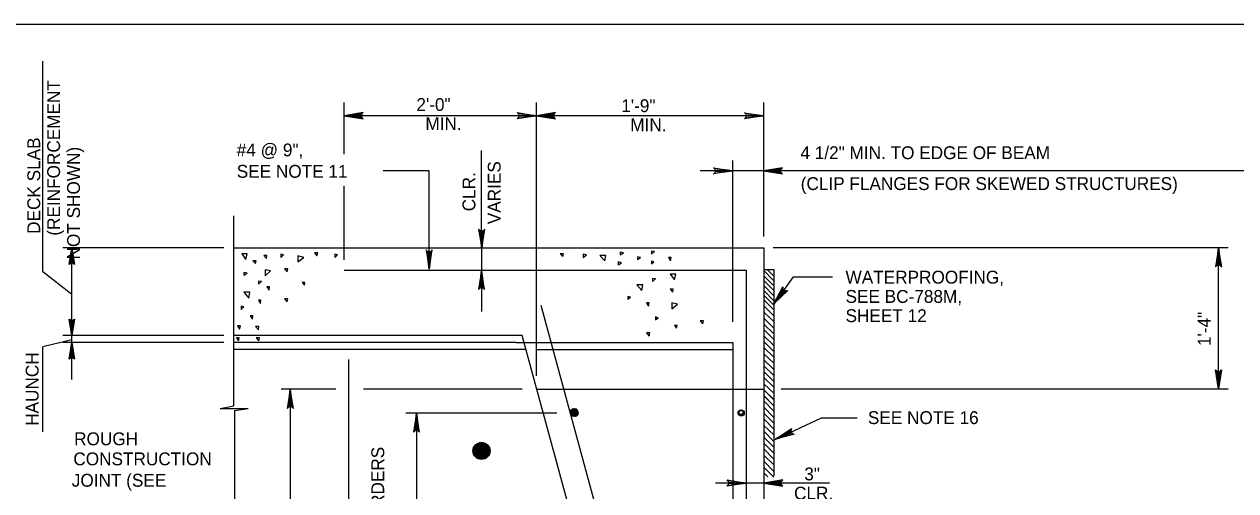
# Model space of a CAD drawing. Extents: x 640009 to 641706, y 298547 to 299735.
# Drawn here: x 640364.1 to 640646.9, y 299017.2 to 299126.2 of the extents above; entities that cross this region are included whole.
import ezdxf

# ---------------------------------------------------------------- set-up
doc = ezdxf.new("R2010")
doc.units = 0
doc.layers.add('1', color=7, linetype='Continuous')

msp = doc.modelspace()

# ---------------------------------------------------------------- linework, layer by layer
at = {"layer": '1'}
for p, q in [((640049.47, 299126.17), (640835.47, 299126.17)), ((640049.47, 299126.17), (640835.47, 299126.17)), ((640368.44, 299068.35), (640368.44, 299117.52)), ((640438.74, 299095.82), (640438.74, 299107.9)), ((640483.65, 299044.02), (640483.65, 299107.9)), ((640536.74, 299076.59), (640536.74, 299107.9)), ((640536.74, 299104.8), (640438.74, 299104.8)), ((640470.86, 299073.94), (640470.86, 299096.68)), ((640529.49, 299056.66), (640529.49, 299094.31)), ((640458.61, 299091.94), (640447.88, 299091.94)), ((640458.61, 299068.94), (640458.61, 299091.94)), ((640529.49, 299091.94), (640521.86, 299091.94)), ((640651.24, 299091.94), (640529.49, 299091.94)), ((640438.74, 299071.13), (640438.74, 299088.4)), ((640412.99, 299037.06), (640412.99, 299081.44)), ((640410.67, 299073.94), (640373.07, 299073.94)), ((640375.21, 299043.2), (640375.21, 299073.94)), ((640412.99, 299073.94), (640536.74, 299073.94)), ((640470.86, 299073.94), (640470.86, 299059.06)), ((640536.74, 299073.94), (640536.74, 299040.94)), ((640536.74, 299073.94), (640536.74, 298959.5)), ((640645.18, 299073.94), (640538.94, 299073.94)), ((640642.91, 299040.94), (640642.91, 299073.94)), ((640375.21, 299063.01), (640368.44, 299068.35)), ((640438.74, 299068.69), (640532.61, 299068.69)), ((640474.74, 299068.69), (640477.26, 299068.69)), ((640532.61, 299068.69), (640532.61, 299014.94)), ((640536.74, 299068.9), (640539.11, 299068.9)), ((640539.11, 299068.9), (640539.11, 299020.68)), ((640539.11, 299060.74), (640543.65, 299067.15)), ((640543.65, 299067.15), (640552.82, 299067.15)), ((640508.11, 298974.56), (640484.77, 299060.46)), ((640375.21, 299052.46), (640368.44, 299050.81)), ((640410.67, 299053.44), (640373.07, 299053.44)), ((640480.36, 299053.44), (640412.99, 299053.44)), ((640505.86, 298959.56), (640480.36, 299053.44)), ((640368.44, 299030.96), (640368.44, 299050.81)), ((640410.67, 299051.81), (640373.07, 299051.81)), ((640478.86, 299051.81), (640412.99, 299051.81)), ((640481.24, 299050.19), (640412.99, 299050.19)), ((640478.86, 299051.81), (640529.49, 299051.81)), ((640483.74, 299050.19), (640529.49, 299050.19)), ((640529.49, 299051.81), (640529.49, 298963.44)), ((640439.82, 299047.83), (640439.82, 298971.99)), ((640436.87, 299040.94), (640424.1, 299040.94)), ((640426.23, 299015.32), (640426.23, 299040.94)), ((640480.33, 299040.94), (640443.31, 299040.94)), ((640483.74, 299040.94), (640536.74, 299040.94)), ((640645.18, 299040.94), (640540.8, 299040.94)), ((640409.86, 299036.44), (640412.99, 299037.06)), ((640409.86, 299036.44), (640416.36, 299036.44)), ((640413.11, 299036.44), (640413.11, 299036.44)), ((640413.24, 299035.94), (640416.36, 299036.44)), ((640413.24, 298985.94), (640413.24, 299035.94)), ((640488.45, 299035.31), (640453.19, 299035.31)), ((640455.68, 299035.31), (640455.68, 298963.44)), ((640539.43, 299029.19), (640550.08, 299034.15)), ((640558.55, 299034.15), (640550.08, 299034.15)), ((640552.11, 299019.01), (640525.47, 299019.01))]:
    msp.add_line(p, q, dxfattribs=at)
for points in [[(640442.98, 299105.34), (640442.8, 299105.02), (640438.74, 299104.8), (640442.98, 299105.34), (640443.19, 299105.52), (640438.74, 299104.8), (640442.8, 299104.6), (640442.96, 299104.3), (640438.74, 299104.8), (640443.19, 299104.07), (640442.96, 299104.3)], [(640479.4, 299105.34), (640479.58, 299105.02), (640483.65, 299104.8), (640479.4, 299105.34), (640479.19, 299105.52), (640483.65, 299104.8), (640479.58, 299104.6), (640479.42, 299104.3), (640483.65, 299104.8), (640479.19, 299104.07), (640479.42, 299104.3)], [(640487.89, 299105.34), (640487.72, 299105.02), (640483.65, 299104.8), (640487.89, 299105.34), (640488.1, 299105.52), (640483.65, 299104.8), (640487.72, 299104.6), (640487.88, 299104.3), (640483.65, 299104.8), (640488.1, 299104.07), (640487.88, 299104.3)], [(640532.45, 299105.32), (640532.62, 299105), (640536.69, 299104.78), (640532.45, 299105.32), (640532.24, 299105.51), (640536.69, 299104.78), (640532.62, 299104.58), (640532.46, 299104.28), (640536.69, 299104.78), (640532.24, 299104.06), (640532.46, 299104.28)], [(640525.2, 299092.46), (640525.37, 299092.14), (640529.44, 299091.92), (640525.2, 299092.46), (640524.99, 299092.65), (640529.44, 299091.92), (640525.37, 299091.72), (640525.21, 299091.42), (640529.44, 299091.92), (640524.99, 299091.2), (640525.21, 299091.42)], [(640540.9, 299092.46), (640540.73, 299092.14), (640536.66, 299091.92), (640540.9, 299092.46), (640541.11, 299092.65), (640536.66, 299091.92), (640540.73, 299091.72), (640540.88, 299091.42), (640536.66, 299091.92), (640541.11, 299091.2), (640540.88, 299091.42)], [(640470.34, 299078.1), (640470.66, 299077.93), (640470.88, 299073.86), (640470.34, 299078.1), (640470.15, 299078.31), (640470.88, 299073.86), (640471.08, 299077.93), (640471.38, 299078.08), (640470.88, 299073.86), (640471.6, 299078.31), (640471.38, 299078.08)], [(640374.71, 299070.19), (640375.09, 299070.31), (640375.21, 299073.94), (640374.71, 299070.19), (640374.59, 299070.06), (640375.21, 299073.94), (640375.46, 299070.31), (640375.71, 299070.19), (640375.21, 299073.94), (640375.84, 299070.06), (640375.71, 299070.19)], [(640458.09, 299073.23), (640458.41, 299073.05), (640458.63, 299068.98), (640458.09, 299073.23), (640457.9, 299073.44), (640458.63, 299068.98), (640458.83, 299073.05), (640459.13, 299073.21), (640458.63, 299068.98), (640459.35, 299073.44), (640459.13, 299073.21)], [(640643.45, 299069.69), (640643.14, 299069.87), (640642.91, 299073.94), (640643.45, 299069.69), (640643.64, 299069.48), (640642.91, 299073.94), (640642.72, 299069.87), (640642.41, 299069.71), (640642.91, 299073.94), (640642.19, 299069.48), (640642.41, 299069.71)], [(640471.38, 299064.4), (640471.07, 299064.57), (640470.85, 299068.64), (640471.38, 299064.4), (640471.57, 299064.19), (640470.85, 299068.64), (640470.65, 299064.57), (640470.34, 299064.42), (640470.85, 299068.64), (640470.12, 299064.19), (640470.34, 299064.42)], [(640539.12, 299066.26), (640536.68, 299068.7)], [(640539.11, 299065.07), (640536.74, 299067.44)], [(640539.11, 299067.33), (640537.54, 299068.9)], [(640539.16, 299062.69), (640536.72, 299065.13)], [(640539.19, 299063.89), (640536.75, 299066.33)], [(640539.11, 299061.57), (640536.82, 299063.86)], [(640542.05, 299063.93), (640541.69, 299063.97), (640539.1, 299060.83), (640542.05, 299063.93), (640542.32, 299063.99), (640539.1, 299060.83), (640541.35, 299064.22), (640541.2, 299064.53), (640539.1, 299060.83), (640541.15, 299064.85), (640541.2, 299064.53)], [(640539.18, 299059.35), (640536.74, 299061.79)], [(640539.11, 299060.54), (640536.75, 299062.9)], [(640539.18, 299057.97), (640536.8, 299060.35)], [(640539.18, 299056.62), (640536.8, 299058.85)], [(640375.71, 299057.19), (640375.46, 299057.06), (640375.21, 299053.44), (640375.71, 299057.19), (640375.84, 299057.31), (640375.21, 299053.44), (640375.09, 299057.06), (640374.84, 299057.19), (640375.21, 299053.44), (640374.59, 299057.31), (640374.84, 299057.19)], [(640539.14, 299053.74), (640536.77, 299056.11)], [(640539.14, 299055.13), (640536.8, 299057.47)], [(640539.18, 299055.1), (640536.8, 299057.47)], [(640539.14, 299052.48), (640536.77, 299054.85)], [(640539.14, 299051.02), (640536.77, 299053.4)], [(640374.71, 299048.06), (640375.09, 299048.19), (640375.21, 299051.81), (640374.71, 299048.06), (640374.59, 299047.94), (640375.21, 299051.81), (640375.46, 299048.19), (640375.71, 299048.06), (640375.21, 299051.81), (640375.84, 299047.94), (640375.71, 299048.06)], [(640539.14, 299049.66), (640536.77, 299052.04)], [(640539.14, 299048.29), (640536.77, 299050.66)], [(640539.14, 299046.93), (640536.77, 299049.16)], [(640539.14, 299045.41), (640536.77, 299047.79)], [(640539.14, 299044.04), (640536.77, 299046.41)], [(640539.14, 299042.66), (640536.77, 299045.04)], [(640643.44, 299045.23), (640643.12, 299045.05), (640642.9, 299040.98), (640643.44, 299045.23), (640643.62, 299045.44), (640642.9, 299040.98), (640642.7, 299045.05), (640642.4, 299045.21), (640642.9, 299040.98), (640642.17, 299045.44), (640642.4, 299045.21)], [(640539.14, 299041.29), (640536.77, 299043.66)], [(640539.14, 299039.93), (640536.77, 299042.16)], [(640426.75, 299036.65), (640426.43, 299036.82), (640426.21, 299040.89), (640426.75, 299036.65), (640426.93, 299036.44), (640426.21, 299040.89), (640426.01, 299036.82), (640425.71, 299036.67), (640426.21, 299040.89), (640425.49, 299036.44), (640425.71, 299036.67)], [(640539.11, 299037.05), (640536.74, 299039.43)], [(640539.11, 299038.44), (640536.77, 299040.79)], [(640539.14, 299038.41), (640536.77, 299040.79)], [(640538.18, 299038), (640536.77, 299039.41)], [(640491.61, 299035.44), (640492.49, 299036.44)], [(640491.61, 299035.19), (640492.86, 299036.44)], [(640491.61, 299035.19), (640492.74, 299036.44)], [(640491.61, 299035.31), (640492.61, 299036.44)], [(640491.61, 299035.44), (640492.49, 299036.44)], [(640491.61, 299035.56), (640492.36, 299036.44)], [(640491.61, 299035.69), (640492.24, 299036.44)], [(640491.61, 299035.94), (640492.11, 299036.31)], [(640491.74, 299034.94), (640493.11, 299036.31)], [(640491.74, 299034.94), (640492.99, 299036.31)], [(640491.74, 299035.06), (640492.86, 299036.31)], [(640491.86, 299034.81), (640493.24, 299036.19)], [(640491.86, 299034.81), (640493.11, 299036.19)], [(640491.99, 299034.69), (640493.24, 299036.06)], [(640491.99, 299034.69), (640493.24, 299036.06)], [(640492.11, 299034.56), (640493.36, 299035.94)], [(640492.11, 299034.56), (640493.36, 299035.94)], [(640492.11, 299034.69), (640493.36, 299035.94)], [(640492.24, 299034.56), (640493.36, 299035.81)], [(640492.36, 299034.56), (640493.49, 299035.69)], [(640492.49, 299034.56), (640493.49, 299035.56)], [(640492.61, 299034.56), (640493.49, 299035.56)], [(640492.74, 299034.56), (640493.49, 299035.44)], [(640539.11, 299035.79), (640536.74, 299038.17)], [(640539.11, 299034.33), (640536.74, 299036.71)], [(640536.81, 299038), (640536.77, 299038.04)], [(640456.21, 299031.07), (640455.9, 299031.24), (640455.68, 299035.31), (640456.21, 299031.07), (640456.4, 299030.86), (640455.68, 299035.31), (640455.48, 299031.24), (640455.17, 299031.09), (640455.68, 299035.31), (640454.95, 299030.86), (640455.17, 299031.09)], [(640492.86, 299034.56), (640493.49, 299035.19)], [(640493.11, 299034.69), (640493.36, 299034.94)], [(640539.11, 299032.98), (640536.74, 299035.35)], [(640539.11, 299031.6), (640536.74, 299033.98)], [(640539.11, 299030.25), (640536.74, 299032.48)], [(640539.11, 299028.73), (640536.74, 299031.1)], [(640543.56, 299030.5), (640543.27, 299030.72), (640539.47, 299029.27), (640543.56, 299030.5), (640543.83, 299030.42), (640539.47, 299029.27), (640543.1, 299031.1), (640543.12, 299031.45), (640539.47, 299029.27), (640543.24, 299031.74), (640543.12, 299031.45)], [(640468.98, 299025.98), (640468.87, 299026.6), (640469.09, 299027.33), (640469.76, 299028.1), (640470.41, 299028.37), (640471.19, 299028.38), (640472.06, 299027.98), (640472.57, 299027.39), (640472.74, 299026.75), (640472.71, 299026.02), (640472.41, 299025.39), (640472.01, 299024.96), (640471.41, 299024.68), (640470.75, 299024.56), (640470.12, 299024.72), (640469.59, 299025.03), (640469.17, 299025.54), (640468.99, 299025.98), (640469, 299027.11), (640469.08, 299025.75), (640469.09, 299027.38), (640469.2, 299025.39), (640469.23, 299027.6), (640469.32, 299025.3), (640469.34, 299027.73), (640469.42, 299025.17), (640469.47, 299027.88), (640469.54, 299025.04), (640469.57, 299028), (640469.66, 299024.98), (640469.67, 299028.05), (640469.74, 299024.89), (640469.76, 299028.16), (640469.8, 299024.85), (640469.86, 299028.19), (640469.9, 299024.81), (640469.93, 299028.24), (640469.98, 299024.77), (640470.01, 299028.29), (640470.09, 299024.66), (640470.09, 299028.32), (640470.21, 299024.65), (640470.15, 299028.34), (640470.34, 299024.62), (640470.28, 299028.38), (640470.49, 299024.58), (640470.38, 299028.39), (640470.43, 299024.6), (640470.47, 299028.44), (640470.58, 299024.57), (640470.57, 299028.43), (640470.67, 299024.55), (640470.65, 299028.45), (640470.75, 299024.54), (640470.72, 299028.45), (640470.88, 299024.57), (640470.82, 299028.45), (640470.97, 299024.55), (640470.92, 299028.48), (640470.82, 299024.54), (640471, 299028.45), (640471.05, 299024.56), (640471.09, 299028.47), (640471.13, 299024.57), (640471.18, 299028.43), (640471.21, 299024.58), (640471.26, 299028.41), (640471.31, 299024.61), (640471.33, 299028.39), (640471.4, 299024.63), (640471.42, 299028.37), (640471.5, 299024.69), (640471.51, 299028.36), (640471.59, 299024.71), (640471.57, 299028.32), (640471.68, 299024.73), (640471.65, 299028.27), (640471.77, 299024.79), (640471.74, 299028.25), (640471.84, 299024.84), (640471.83, 299028.2), (640471.91, 299024.86), (640471.93, 299028.14), (640471.99, 299024.93), (640472, 299028.09), (640472.05, 299024.99), (640472.09, 299028.01), (640472.15, 299025.08), (640472.19, 299027.9), (640472.26, 299025.17), (640472.29, 299027.78), (640472.4, 299025.31), (640472.36, 299027.7), (640472.52, 299025.55), (640472.47, 299027.61), (640472.47, 299025.48), (640472.54, 299027.48), (640472.57, 299025.63), (640472.63, 299027.31), (640472.64, 299025.76), (640472.7, 299027.11)], [(640472.7, 299027.11), (640472.79, 299026.42), (640472.12, 299025.39), (640470.74, 299024.76), (640469.18, 299025.69), (640469.02, 299027.04), (640470.22, 299028.08), (640471.5, 299028.08), (640472.45, 299027.42), (640472.66, 299026.34), (640472.02, 299025.12), (640472.39, 299025.56), (640470.35, 299024.79), (640469.22, 299025.52), (640468.91, 299026.59), (640469.27, 299027.39), (640470.04, 299028.06), (640470.68, 299028.35), (640471.94, 299028)], [(640539.11, 299027.35), (640536.74, 299029.73)], [(640539.11, 299025.98), (640536.74, 299028.35)], [(640539.11, 299024.6), (640536.74, 299026.98)], [(640539.11, 299023.25), (640536.74, 299025.48)], [(640539.11, 299021.73), (640536.74, 299024.1)], [(640539.11, 299020.35), (640536.74, 299022.73)], [(640537.67, 299020.42), (640536.74, 299021.35)], [(640528.37, 299019.54), (640528.54, 299019.23), (640532.61, 299019.01), (640528.37, 299019.54), (640528.16, 299019.73), (640532.61, 299019.01), (640528.54, 299018.81), (640528.38, 299018.5), (640532.61, 299019.01), (640528.16, 299018.28), (640528.38, 299018.5)], [(640540.98, 299019.54), (640540.8, 299019.23), (640536.74, 299019.01), (640540.98, 299019.54), (640541.19, 299019.73), (640536.74, 299019.01), (640540.8, 299018.81), (640540.96, 299018.5), (640536.74, 299019.01), (640541.19, 299018.28), (640540.96, 299018.5)]]:
    msp.add_lwpolyline(points, dxfattribs=at)
for points in [[(640414.86, 299072.56), (640415.86, 299071.19), (640416.11, 299072.56)], [(640419.99, 299072.19), (640420.61, 299071.44), (640420.74, 299072.19)], [(640423.99, 299071.69), (640424.61, 299072.31), (640423.99, 299072.44)], [(640431.86, 299072.81), (640432.36, 299072.06), (640432.61, 299072.81)], [(640436.61, 299071.69), (640437.24, 299072.31), (640436.61, 299072.44)], [(640489.24, 299072.56), (640489.86, 299071.94), (640489.99, 299072.56)], [(640494.61, 299071.69), (640495.36, 299072.31), (640494.61, 299072.44)], [(640498.49, 299072.19), (640499.61, 299070.94), (640499.86, 299072.19)], [(640503.24, 299072.31), (640503.99, 299072.81), (640503.24, 299072.94)], [(640510.49, 299072.44), (640511.24, 299073.06), (640510.49, 299073.19)], [(640417.49, 299070.94), (640418.11, 299070.31), (640418.24, 299070.94)], [(640427.99, 299070.69), (640429.36, 299071.69), (640427.99, 299072.06)], [(640502.74, 299069.94), (640503.49, 299070.44), (640502.74, 299070.69)], [(640507.24, 299071.19), (640507.99, 299071.69), (640507.24, 299071.81)], [(640510.49, 299070.19), (640511.11, 299070.69), (640510.49, 299070.81)], [(640514.49, 299071.69), (640514.99, 299070.94), (640515.11, 299071.69)], [(640415.36, 299067.56), (640416.11, 299068.06), (640415.36, 299068.19)], [(640420.36, 299067.44), (640421.61, 299068.56), (640420.36, 299068.81)], [(640424.86, 299069.06), (640425.49, 299068.31), (640425.61, 299069.06)], [(640510.74, 299066.06), (640511.49, 299066.69), (640510.74, 299066.81)], [(640514.86, 299067.81), (640515.86, 299066.44), (640516.24, 299067.81)], [(640418.74, 299065.44), (640419.49, 299066.06), (640418.74, 299066.19)], [(640420.74, 299064.81), (640421.24, 299064.06), (640421.36, 299064.81)], [(640428.99, 299065.81), (640429.49, 299065.19), (640429.61, 299065.81)], [(640507.11, 299065.31), (640508.24, 299063.94), (640508.49, 299065.31)], [(640514.86, 299064.31), (640515.49, 299063.56), (640515.61, 299064.31)], [(640415.36, 299063.56), (640416.49, 299062.19), (640416.74, 299063.56)], [(640418.74, 299061.69), (640419.24, 299060.94), (640419.36, 299061.69)], [(640424.86, 299062.06), (640425.49, 299061.31), (640425.61, 299062.06)], [(640504.99, 299061.94), (640505.61, 299062.44), (640504.99, 299062.56)], [(640509.36, 299061.06), (640509.86, 299060.31), (640509.99, 299061.06)], [(640515.24, 299059.69), (640516.61, 299060.81), (640515.24, 299061.06)], [(640414.74, 299059.56), (640415.36, 299060.19), (640414.74, 299060.31)], [(640416.86, 299058.06), (640417.36, 299057.31), (640417.49, 299058.06)], [(640413.86, 299055.69), (640414.36, 299054.94), (640414.61, 299055.69)], [(640418.11, 299055.56), (640418.74, 299054.81), (640418.86, 299055.56)], [(640511.43, 299057.11), (640512.06, 299057.61), (640511.43, 299057.86)], [(640515.86, 299055.81), (640516.36, 299055.19), (640516.49, 299055.81)], [(640521.89, 299056.91), (640522.52, 299056.16), (640522.64, 299056.91)], [(640413.61, 299052.94), (640414.11, 299052.19), (640414.24, 299052.94)], [(640418.24, 299052.94), (640418.86, 299052.19), (640418.99, 299052.94)], [(640509.36, 299054.06), (640509.99, 299053.31), (640510.11, 299054.06)]]:
    msp.add_lwpolyline(points, close=True, dxfattribs=at)
for centre, radius in [((640531.38, 299035.43), 0.636), ((640531.49, 299035.37), 0.693), ((640531.44, 299035.49), 0.474), ((640470.83, 299026.51), 2)]:
    msp.add_circle(centre, radius, dxfattribs=at)

# ---------------------------------------------------------------- texts
for s, p in [('(REINFORCEMENT', (640372.45, 299076.79)), ('DECK SLAB', (640367.81, 299077.21)), ('   NOT SHOWN)', (640377.1, 299067.89)), ('VARIES', (640475.31, 299079.46)), ('CLR.', (640469.41, 299082.47)), ('1\'-4"', (640641.06, 299051)), ('HAUNCH', (640367.44, 299032.37)), ('WELD FOR PLATE GIRDERS', (640448.12, 298973.08))]:
    msp.add_text(s, height=3, rotation=90, dxfattribs=at).set_placement(p)
for s, p in [('2\'-0"', (640455.64, 299105.92)), ('1\'-9"', (640503.47, 299105.64)), ('MIN.', (640457.74, 299101.44)), ('MIN.', (640505.57, 299101.16)), ('#4 @ 9",', (640413.7, 299095.31)), ('4 1/2" MIN. TO EDGE OF BEAM', (640545.3, 299094.66)), ('SEE NOTE 11', (640413.7, 299090.31)), ('(CLIP FLANGES FOR SKEWED STRUCTURES)', (640545.36, 299087.44)), ('WATERPROOFING,', (640555.83, 299065.59)), ('SEE BC-788M,', (640555.83, 299061.09)), ('SHEET 12', (640555.83, 299056.59)), ('SEE NOTE 16', (640561.04, 299032.78)), ('ROUGH', (640375.74, 299027.83)), ('CONSTRUCTION', (640375.55, 299023.15)), ('JOINT (SEE', (640375.19, 299018.15)), ('3"', (640546.2, 299019.63)), ('CLR.', (640543.81, 299015.14))]:
    msp.add_text(s, height=3, dxfattribs=at).set_placement(p)

doc.saveas('drawing.dxf')
